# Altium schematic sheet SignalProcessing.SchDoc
size A4
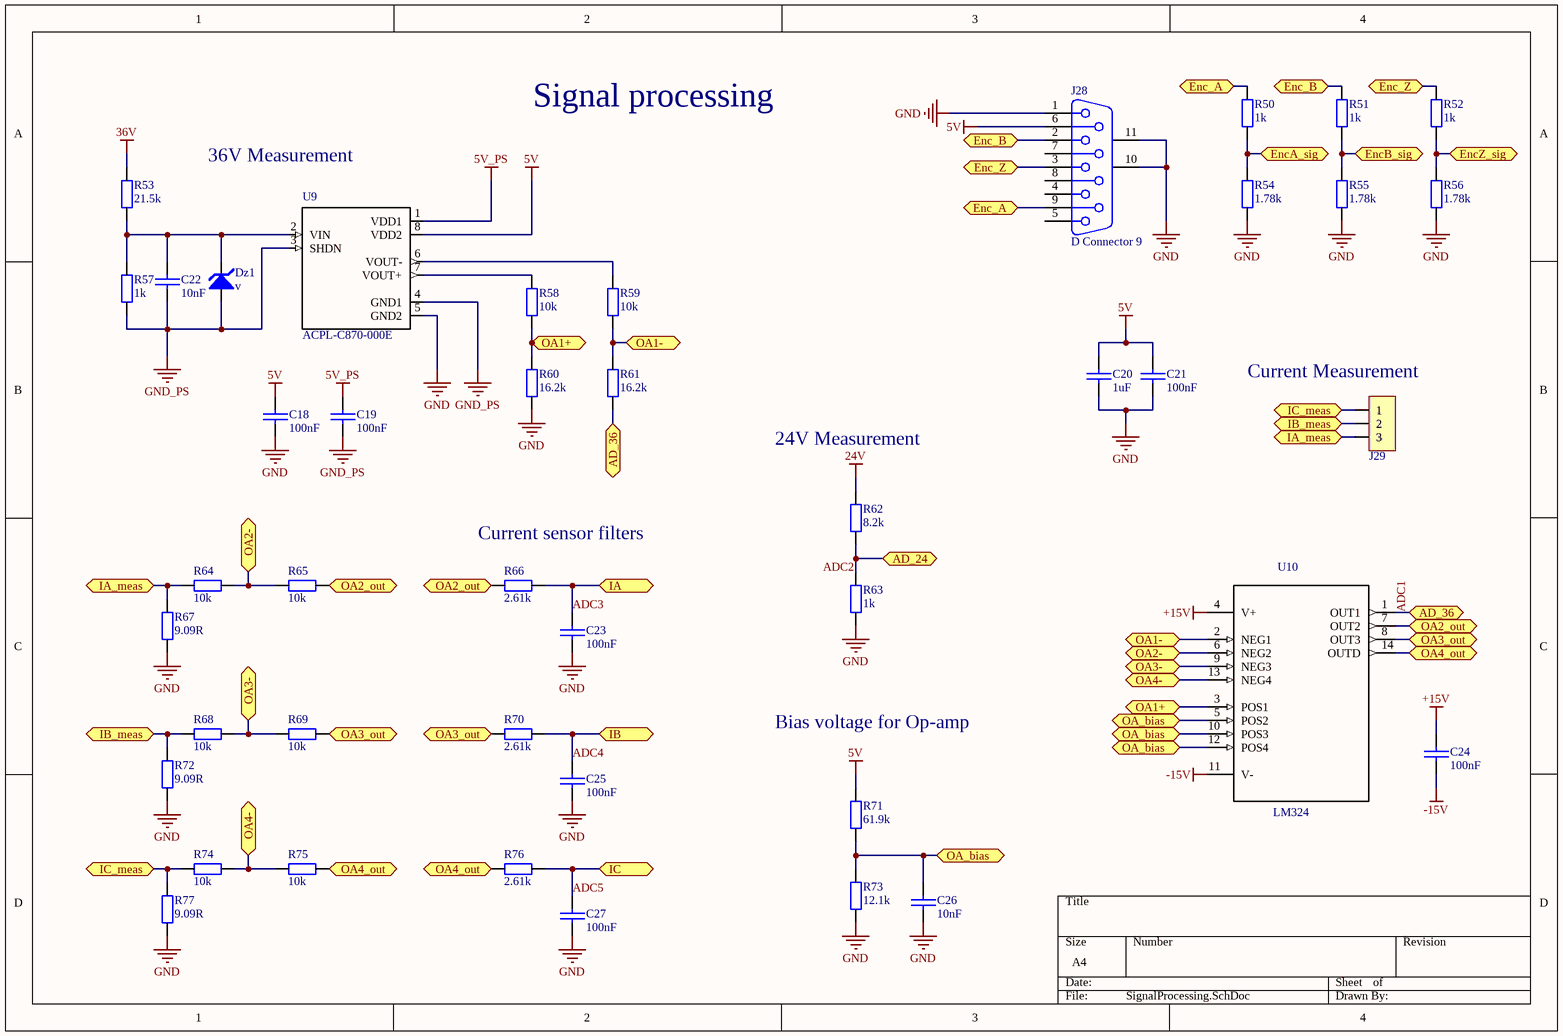
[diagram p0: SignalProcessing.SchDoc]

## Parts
C18  100nF  [1206]
C19  100nF  [1206]
C20  1uF  [1206]
C21  100nF  [1206]
C22  10nF  [1206]
C23  100nF  [1206]
C24  100nF  [1206]
C25  100nF  [1206]
C26  10nF  [1206]
C27  100nF  [1206]
Dz1  v  [Diodo]
J28  D Connector 9  [DSUB1.385-2H9]
J29  Cleva 2 vias  [Con3_KK_256]  (value not drawn)
R50  1k  [1206]
R51  1k  [1206]
R52  1k  [1206]
R53  21.5k  [1206]
R54  1.78k  [1206]
R55  1.78k  [1206]
R56  1.78k  [1206]
R57  1k  [1206]
R58  10k  [1206]
R59  10k  [1206]
R60  16.2k  [1206]
R61  16.2k  [1206]
R62  8.2k  [1206]
R63  1k  [1206]
R64  10k  [1206]
R65  10k  [1206]
R66  2.61k  [1206]
R67  9.09R  [1206]
R68  10k  [1206]
R69  10k  [1206]
R70  2.61k  [1206]
R71  61.9k  [1206]
R72  9.09R  [1206]
R73  12.1k  [1206]
R74  10k  [1206]
R75  10k  [1206]
R76  2.61k  [1206]
R77  9.09R  [1206]
U9  ACPL-C870-000E  [SOIC127P1150X360-8N]
U10  LM324  [SOIC_14]

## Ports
AD_24, AD_36, Enc_A, Enc_B, Enc_Z, EncA_sig, EncB_sig, EncZ_sig, IA, IA_meas, IB, IB_meas, IC, IC_meas, OA1+, OA1-, OA2-, OA2_out, OA3-, OA3_out, OA4-, OA4_out, OA_bias

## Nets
5V: C18.1 C20.2 C21.2 J28.6 R71.2 U9.8(VDD2)
5V_PS: C19.1 U9.1(VDD1)
24V: R62.1
36V: R53.2
+15V: C24.1 U10.4(V+)
-15V: C24.2 U10.11(V-)
GND: C18.2 C20.1 C21.1 C23.1 C25.2 C26.2 C27.1 J28.1 J28.10(MH1) J28.11(MH2) R54.1 R55.1 R56.1 R60.1 R63.1 R67.2 R72.2 R73.2 R77.1 U9.5(GND2)
GND_PS: C19.2 C22.2 Dz1.1(A) R57.2 U9.3(SHDN) U9.4(GND1)
ADC1: R61.1 U10.1(OUT1) ; port AD_36
ADC2: R62.2 R63.2 ; port AD_24
ADC3: C23.2 R66.2 ; port IA
ADC4: C25.1 R70.1 ; port IB
ADC5: C27.2 R76.2 ; port IC
Enc_A: J28.9 R50.2 ; port Enc_A
Enc_B: J28.2 R51.2 ; port Enc_B
Enc_Z: J28.3 R52.2 ; port Enc_Z
EncA_sig: R50.1 R54.2 ; port EncA_sig
EncB_sig: R51.1 R55.2 ; port EncB_sig
EncZ_sig: R52.1 R56.2 ; port EncZ_sig
IA_meas: J29.3 R64.1 R67.1 ; port IA_meas
IB_meas: J29.2 R68.1 R72.1 ; port IB_meas
IC_meas: J29.1 R74.2 R77.2 ; port IC_meas
OA1+: R58.1 R60.2 U10.3(POS1) ; port OA1+
OA1-: R59.1 R61.2 U10.2(NEG1) ; port OA1-
OA2-: R64.2 R65.2 U10.6(NEG2) ; port OA2-
OA2_out: R65.1 R66.1 U10.7(OUT2) ; port OA2_out
OA3-: R68.2 R69.1 U10.9(NEG3) ; port OA3-
OA3_out: R69.2 R70.2 U10.8(OUT3) ; port OA3_out
OA4-: R74.1 R75.2 U10.13(NEG4) ; port OA4-
OA4_out: R75.1 R76.1 U10.14(OUTD) ; port OA4_out
OA_bias: C26.1 R71.1 R73.1 U10.5(POS2) U10.10(POS3) U10.12(POS4) ; port OA_bias
NetC22_1: C22.1 Dz1.2(K) R53.1 R57.1 U9.2(VIN)
NetR58_2: R58.2 U9.7(VOUT+)
NetR59_2: R59.2 U9.6(VOUT-)

Not connected (* = marked no-connect by the designer): J28 4 5 7 8

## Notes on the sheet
- Signal processing
- 36V Measurement
- (near J29) Current Measurement
- 24V Measurement
- (near R66) Current sensor filters
- Bias voltage for Op-amp

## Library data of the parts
C18-C27 = Condensador
Dz1 = Zener
J28 = D Connector 9: Receptacle Assembly, 9 Position, Right Angle; PackageDocument: O; Positions: 9
J29 = Con_3
R50-R77 = Resistencia: Potencia: 1/4W
U9 = ACPL-C870-000E: Isolation Amplifier [Broadcom] ACPL-C870-000E Isolation Amplifier; MF: Broadcom Limited
U10 = LMC6484IM_1: 14 pin CMOS Quad Rail to Rail Input and Output Operational Amplifier 55 per tube; MF: Texas Instruments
